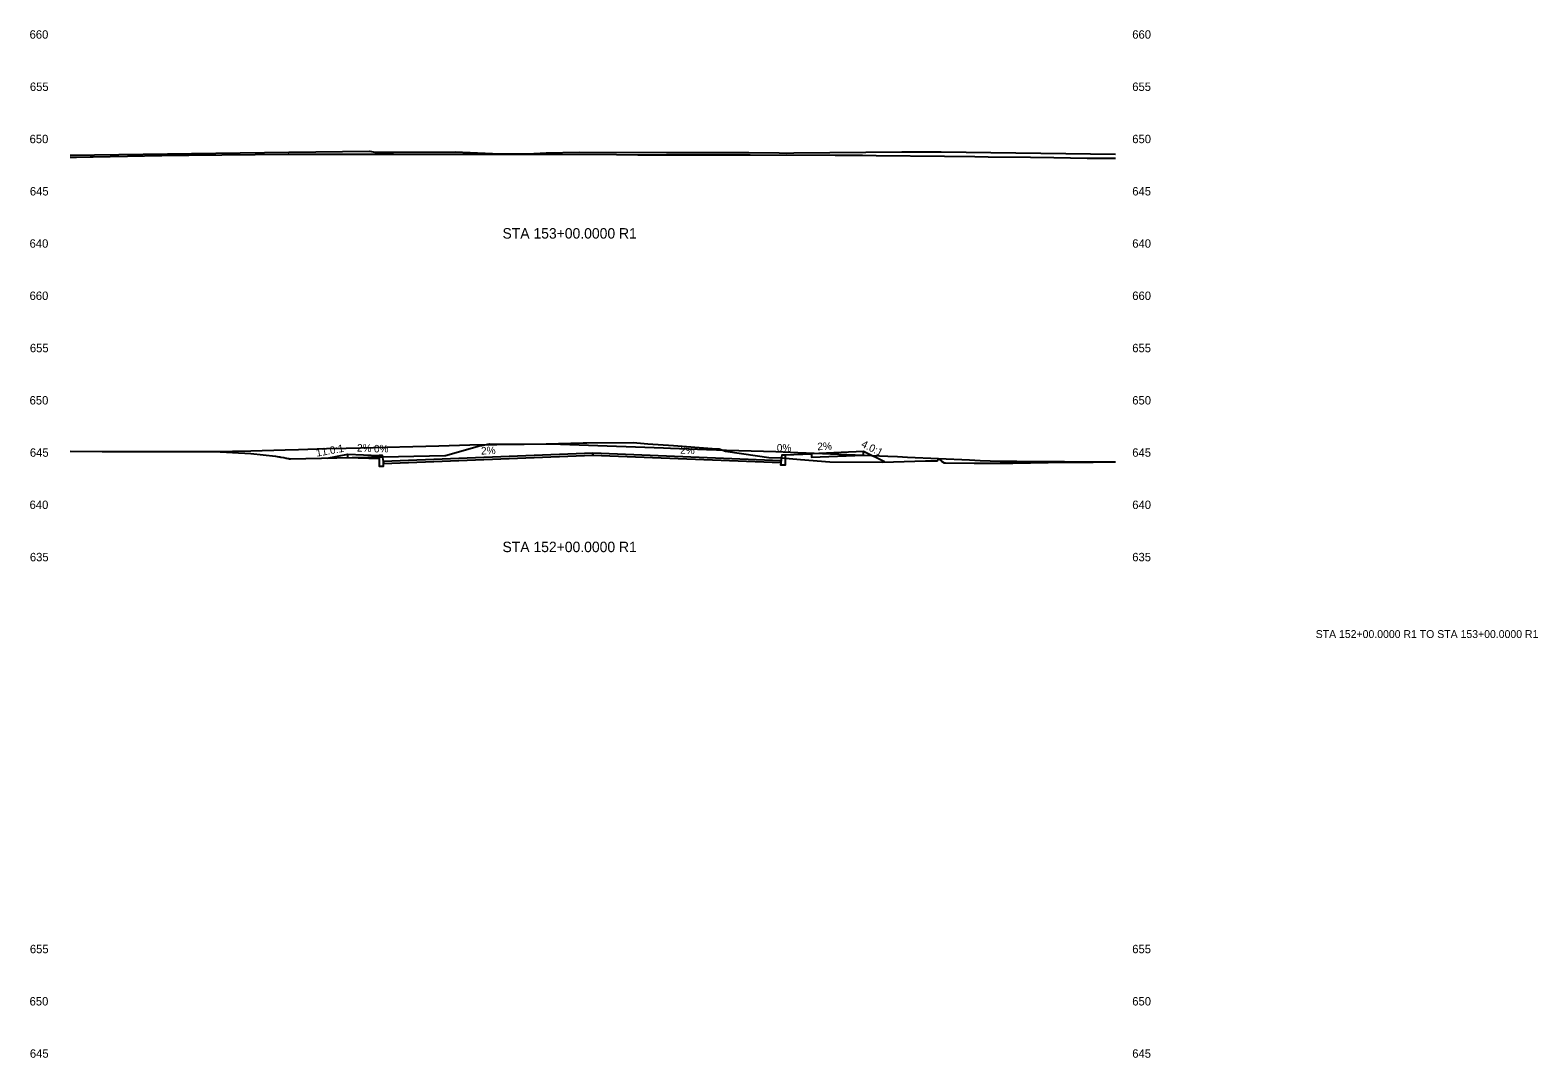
# Model space of a CAD drawing. Extents: x 12 to 301, y 16 to 1707.
# Drawn here: x 12.4 to 300.8, y 1510.6 to 1707.2 of the extents above; entities that cross this region are included whole.
import ezdxf

# ---------------------------------------------------------------- set-up
doc = ezdxf.new("R2010")
doc.units = 0
for name, color, linetype in [('BORD_text_large_2', 7, 'Continuous'), ('Default', 7, 'Continuous'), ('Draft_XS_Point_Label_Indicator', 7, 'Continuous'), ('Draft_XS_Text', 7, 'Continuous'), ('Grade_Veg_Grass', 7, 'Continuous'), ('P_XS_Sections', 7, 'Continuous'), ('Road_Curb', 7, 'Continuous'), ('Road_Pave_Asphalt', 7, 'Continuous'), ('Road_Sidewalk', 7, 'Continuous'), ('Terrain_Exterior', 7, 'Continuous')]:
    doc.layers.add(name, color=color, linetype=linetype)

msp = doc.modelspace()

# ---------------------------------------------------------------- linework, layer by layer
at = {"layer": 'Default'}
for points in [[(20, 1683.31), (61.87, 1683.91), (77.32, 1684.07), (77.38, 1684.07), (78.34, 1683.91), (81.87, 1683.89), (93.68, 1683.93), (102.32, 1683.56), (108.72, 1683.63), (111.11, 1683.75), (117.41, 1683.9), (134.13, 1683.8), (149.87, 1683.83), (155.69, 1683.73), (156.99, 1683.71), (158.49, 1683.77), (179.16, 1683.92), (179.86, 1683.96), (179.89, 1683.96), (180.63, 1683.96), (184.9, 1683.94), (186.67, 1683.92), (220, 1683.48)], [(20, 1626.64), (26.12, 1626.63), (33.7, 1626.6), (47.6, 1626.62), (54.62, 1626.24), (59.29, 1625.73), (59.95, 1625.61), (60.17, 1625.57), (60.35, 1625.53), (60.91, 1625.43), (61.32, 1625.35), (61.36, 1625.35), (61.39, 1625.34), (61.65, 1625.29), (61.8, 1625.26), (61.83, 1625.26), (61.86, 1625.26), (61.86, 1625.26), (61.86, 1625.26), (62.01, 1625.23), (62.12, 1625.21), (62.13, 1625.2), (62.14, 1625.2), (62.18, 1625.2), (91.71, 1625.83), (91.79, 1625.83), (91.85, 1625.84), (97.91, 1627.56), (98.1, 1627.61), (98.62, 1627.77), (98.77, 1627.78), (100.28, 1628.04), (101.26, 1628.01), (111.11, 1628.06), (118.17, 1628.28), (118.71, 1628.27), (118.89, 1628.27), (127.73, 1628.34), (130.54, 1628.07), (135.48, 1627.73), (142.82, 1627.18), (143.33, 1627.14), (143.65, 1627.1), (144.18, 1627.11), (145.4, 1626.7), (151.52, 1625.78), (153.71, 1625.47), (156.09, 1625.37), (159.74, 1625.06), (165.39, 1624.61), (175.49, 1624.59), (183.68, 1624.8), (184.09, 1624.83), (185.88, 1624.79), (186.12, 1625.1), (186.21, 1625.23), (186.75, 1624.78), (187.25, 1624.42), (187.51, 1624.44), (192.98, 1624.37), (196.28, 1624.39), (198.52, 1624.38), (200.37, 1624.4), (210.5, 1624.54), (211.57, 1624.55), (211.97, 1624.55), (212.11, 1624.56), (212.21, 1624.55), (212.38, 1624.55), (215.75, 1624.59), (219.46, 1624.62), (219.58, 1624.62), (220, 1624.63)]]:
    msp.add_lwpolyline(points, dxfattribs=at)
at = {"layer": 'Grade_Veg_Grass'}
for points in [[(69.17, 1625.35), (73.17, 1626.07), (73.17, 1626.07)], [(156.83, 1625.99), (161.83, 1626.19)], [(175.83, 1624.6), (171.83, 1626.59), (171.83, 1626.59)]]:
    msp.add_lwpolyline(points, dxfattribs=at)
at = {"layer": 'Road_Curb'}
for points in [[(79.17, 1625.83), (79.17, 1623.83), (80, 1623.83), (80, 1624.67), (79.77, 1625.83), (79.17, 1625.83)], [(156.83, 1625.99), (156.83, 1623.99), (156, 1623.99), (156.23, 1625.99), (156.83, 1625.99)]]:
    msp.add_lwpolyline(points, dxfattribs=at)
at = {"layer": 'Road_Pave_Asphalt'}
for points in [[(120, 1626.27), (80, 1624.67), (80, 1624.67), (80, 1624.33), (120, 1625.93), (120, 1625.93), (120, 1626.27), (120, 1626.27), (120, 1626.27)], [(120, 1626.27), (120, 1626.27), (120, 1626.27), (120, 1625.93), (120, 1625.93), (156, 1624.49), (156, 1624.83), (156, 1624.83), (120, 1626.27)]]:
    msp.add_lwpolyline(points, dxfattribs=at)
at = {"layer": 'Road_Sidewalk'}
for points in [[(79.17, 1625.83), (79.17, 1625.17), (73.17, 1625.41), (73.17, 1626.07), (79.17, 1625.83)], [(161.83, 1626.19), (161.83, 1625.53), (171.83, 1625.93), (171.83, 1626.59), (161.83, 1626.19)]]:
    msp.add_lwpolyline(points, dxfattribs=at)
at = {"layer": 'Terrain_Exterior'}
for points in [[(20, 1682.93), (21.24, 1682.95), (23.88, 1682.99), (24.43, 1683), (40.81, 1683.28), (41.7, 1683.29), (42.73, 1683.31), (61.74, 1683.47), (64.21, 1683.49), (82.67, 1683.5), (85.69, 1683.5), (103.59, 1683.53), (107.17, 1683.51), (124.52, 1683.42), (128.66, 1683.39), (145.45, 1683.37), (150.14, 1683.36), (166.38, 1683.34), (168.81, 1683.32), (171.62, 1683.3), (174.2, 1683.27), (187.31, 1683.11), (193.1, 1683.03), (195.67, 1683), (203.77, 1682.9), (208.23, 1682.84), (214.58, 1682.76), (220, 1682.71)], [(20, 1626.64), (26.12, 1626.63), (33.7, 1626.6), (47.6, 1626.62), (54.62, 1626.74), (61.19, 1626.93), (63.68, 1627), (69.08, 1627.16), (72.82, 1627.23), (75.55, 1627.28), (90.56, 1627.68), (96.48, 1627.91), (112.05, 1628.07), (117.41, 1627.88), (133.53, 1627.28), (134.86, 1627.23), (138.34, 1627.11), (141.79, 1627), (145.57, 1626.88), (155.01, 1626.58), (159.26, 1626.4), (176.49, 1625.71), (178.29, 1625.62), (180.19, 1625.52), (192.1, 1625), (194.15, 1624.91), (197.98, 1624.74), (201.12, 1624.74), (219.46, 1624.63), (220, 1624.63)]]:
    msp.add_lwpolyline(points, dxfattribs=at)

# ---------------------------------------------------------------- texts
at = {"layer": 'BORD_text_large_2'}
msp.add_text('STA 152+00.0000 R1 TO STA 153+00.0000 R1', height=1.5, dxfattribs=at).set_placement((258.32, 1590.92))
at = {"layer": 'Draft_XS_Point_Label_Indicator'}
for p in [(119.99, 1679.62), (69.16, 1625.33), (73.16, 1626.06), (79.16, 1625.82), (79.76, 1625.82), (79.99, 1624.66), (119.99, 1626.26), (119.99, 1626.26), (155.99, 1624.82), (156.22, 1625.98), (156.82, 1625.98), (161.82, 1626.18), (171.82, 1626.58), (175.82, 1624.59)]:
    msp.add_text('X', height=0.024, dxfattribs=at).set_placement(p)
at = {"layer": 'Draft_XS_Text'}
for s, height, p in [('660', 1.608, (12.26, 1705.6)), ('660', 1.608, (223.22, 1705.6)), ('655', 1.608, (12.32, 1695.6)), ('655', 1.608, (223.22, 1695.6)), ('650', 1.608, (12.26, 1685.6)), ('650', 1.608, (223.22, 1685.6)), ('645', 1.608, (12.32, 1675.6)), ('645', 1.608, (223.22, 1675.6)), ('640', 1.608, (12.26, 1665.6)), ('STA 153+00.0000 R1', 1.992, (102.74, 1667.35)), ('640', 1.608, (223.22, 1665.6)), ('660', 1.608, (12.26, 1655.6)), ('660', 1.608, (223.22, 1655.6)), ('655', 1.608, (12.32, 1645.6)), ('655', 1.608, (223.22, 1645.6)), ('650', 1.608, (12.26, 1635.6)), ('650', 1.608, (223.22, 1635.6)), ('645', 1.608, (12.32, 1625.6)), ('0%', 1.44, (78.15, 1626.43)), ('0%', 1.44, (78.15, 1626.43)), ('0%', 1.44, (78.15, 1626.43)), ('645', 1.608, (223.22, 1625.6)), ('640', 1.608, (12.26, 1615.6)), ('640', 1.608, (223.22, 1615.6)), ('635', 1.608, (12.32, 1605.6)), ('STA 152+00.0000 R1', 1.992, (102.74, 1607.35)), ('635', 1.608, (223.22, 1605.6)), ('655', 1.608, (12.32, 1530.6)), ('655', 1.608, (223.22, 1530.6)), ('650', 1.608, (12.26, 1520.6)), ('650', 1.608, (223.22, 1520.6)), ('645', 1.608, (12.32, 1510.6)), ('645', 1.608, (223.22, 1510.6))]:
    msp.add_text(s, height=height, dxfattribs=at).set_placement(p)
for s, rotation, p in [('11.0:1', 10.3209, (67.21, 1625.6)), ('11.0:1', 10.3209, (67.21, 1625.6)), ('11.0:1', 10.3209, (67.21, 1625.6)), ('2%', 357.7094, (74.88, 1626.61)), ('2%', 357.7094, (74.88, 1626.61)), ('2%', 357.7094, (74.88, 1626.61)), ('2%', 2.2906, (98.66, 1626.01)), ('2%', 2.2906, (98.66, 1626.01)), ('2%', 2.2906, (98.66, 1626.01)), ('2%', 357.7094, (136.71, 1626.2)), ('2%', 357.7094, (136.71, 1626.2)), ('2%', 357.7094, (136.71, 1626.2)), ('0%', 0, (155.22, 1626.59)), ('0%', 0, (155.22, 1626.59)), ('0%', 0, (155.22, 1626.59)), ('2%', 2.2906, (163, 1626.84)), ('2%', 2.2906, (163, 1626.84)), ('2%', 2.2906, (163, 1626.84)), ('4.0:1', 333.4697, (171.24, 1627.56)), ('4.0:1', 333.4697, (171.24, 1627.56)), ('4.0:1', 333.4697, (171.24, 1627.56))]:
    msp.add_text(s, height=1.44, rotation=rotation, dxfattribs=at).set_placement(p)
at = {"layer": 'P_XS_Sections'}
for p in [(20, 1665), (20, 1605)]:
    msp.add_text('-', height=0.0001, dxfattribs=at).set_placement(p)

doc.saveas('drawing.dxf')
